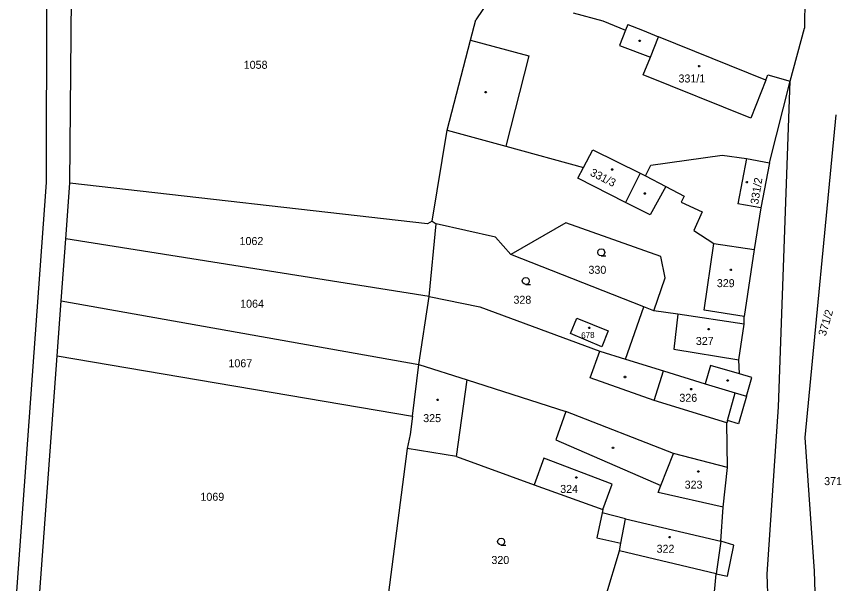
# Model space of a CAD drawing. Extents: x -812394 to -807601, y -1013097 to -1009266.
# Drawn here: x -811179.2 to -811005.4, y -1011411.9 to -1011291.2 of the extents above; entities that cross this region are included whole.
import ezdxf

# ---------------------------------------------------------------- set-up
doc = ezdxf.new("R2010")
doc.units = 0
for name, color, linetype in [('Default', 7, 'Continuous'), ('KN_HRANICE', 7, 'Continuous'), ('KN_KULTURY', 7, 'Continuous'), ('KN_PARCELY', 7, 'Continuous'), ('KN_SLUCKY', 7, 'Continuous')]:
    doc.layers.add(name, color=color, linetype=linetype)

# ---------------------------------------------------------------- blocks, each defined once
blk = doc.blocks.new('304')
at = {"layer": 'Default'}
blk.add_lwpolyline([(0, 0), (-0.38, 0.1), (-0.65, 0.37), (-0.75, 0.74), (-0.65, 1.11), (-0.38, 1.38), (-0.01, 1.48), (0.36, 1.38), (0.63, 1.11), (0.73, 0.73), (0.63, 0.35), (0.36, 0.08), (-0.02, -0.02), (0.98, -0.02)], dxfattribs=at)
blk = doc.blocks.new('NAHRADNI_SYMBOL')
at = {"layer": 'Default'}
blk.add_lwpolyline([(0.09, 0.15), (0.18, 0), (0.09, -0.15), (-0.09, -0.15), (-0.18, 0), (-0.09, 0.15), (0.09, 0.15)], dxfattribs=at)
blk = doc.blocks.new('402')
at = {"layer": 'Default'}
blk.add_lwpolyline([(0.09, 0.15), (0.18, 0), (0.09, -0.15), (-0.09, -0.15), (-0.18, 0), (-0.09, 0.15), (0.09, 0.15)], dxfattribs=at)

msp = doc.modelspace()

# ---------------------------------------------------------------- linework, layer by layer
at = {"layer": 'KN_HRANICE'}
for p, q in [((-811172.71, -1011212.32), (-811172.89, -1011326.55)), ((-811167.89, -1011326.74), (-811167.33, -1011261.3)), ((-811011.7, -1011272.27), (-811011.75, -1011293.77)), ((-811078.49, -1011287.34), (-811081.65, -1011291.97)), ((-811060.91, -1011290.53), (-811054.65, -1011292.2)), ((-811082.78, -1011296.33), (-811081.65, -1011291.97)), ((-811054.65, -1011292.2), (-811049.79, -1011294.2)), ((-811049.3, -1011292.98), (-811049.79, -1011294.2)), ((-811049.3, -1011292.98), (-811046.23, -1011294.21)), ((-811046.23, -1011294.21), (-811042.77, -1011295.58)), ((-811014.86, -1011305), (-811011.75, -1011293.77)), ((-811087.72, -1011315.45), (-811082.78, -1011296.33)), ((-811019.97, -1011304.8), (-811042.77, -1011295.58)), ((-811019.97, -1011304.8), (-811019.54, -1011303.71)), ((-811019.54, -1011303.71), (-811014.86, -1011305)), ((-811019.24, -1011322.42), (-811014.86, -1011305)), ((-811017.29, -1011374.24), (-811014.86, -1011305)), ((-811011.64, -1011380.82), (-811005.05, -1011312.16)), ((-811090.93, -1011334.76), (-811087.72, -1011315.45)), ((-811087.72, -1011315.45), (-811075.23, -1011318.84)), ((-811075.23, -1011318.84), (-811058.77, -1011323.4)), ((-811058.77, -1011323.4), (-811056.78, -1011319.65)), ((-811056.78, -1011319.65), (-811046.67, -1011324.57)), ((-811044.44, -1011322.9), (-811029.3, -1011320.76)), ((-811029.3, -1011320.76), (-811024.13, -1011321.49)), ((-811024.13, -1011321.49), (-811019.24, -1011322.42)), ((-811019.24, -1011322.42), (-811021.08, -1011331.96)), ((-811059.96, -1011325.63), (-811058.77, -1011323.4)), ((-811045.56, -1011325.16), (-811044.44, -1011322.9)), ((-811049.8, -1011330.85), (-811059.96, -1011325.63)), ((-811046.67, -1011324.57), (-811049.8, -1011330.85)), ((-811046.67, -1011324.57), (-811045.56, -1011325.16)), ((-811045.56, -1011325.16), (-811041.24, -1011327.41)), ((-811172.89, -1011326.55), (-811179.25, -1011413.51)), ((-811168.76, -1011338.54), (-811167.89, -1011326.74)), ((-811091.86, -1011335.35), (-811167.89, -1011326.74)), ((-811041.24, -1011327.41), (-811037.33, -1011329.45)), ((-811037.33, -1011329.45), (-811038.01, -1011330.76)), ((-811038.01, -1011330.76), (-811033.52, -1011332.81)), ((-811033.52, -1011332.81), (-811035.32, -1011336.75)), ((-811021.08, -1011331.96), (-811022.45, -1011340.81)), ((-811090.93, -1011334.76), (-811091.86, -1011335.35)), ((-811090.93, -1011334.76), (-811090.07, -1011335.38)), ((-811091.55, -1011350.81), (-811090.07, -1011335.38)), ((-811077.44, -1011338.22), (-811090.07, -1011335.38)), ((-811062.47, -1011335.13), (-811074.19, -1011341.86)), ((-811042.3, -1011342.3), (-811062.47, -1011335.13)), ((-811074.19, -1011341.86), (-811077.44, -1011338.22)), ((-811035.32, -1011336.75), (-811031.07, -1011339.53)), ((-811169.72, -1011351.73), (-811168.76, -1011338.54)), ((-811091.55, -1011350.81), (-811168.76, -1011338.54)), ((-811031.07, -1011339.53), (-811022.45, -1011340.81)), ((-811022.45, -1011340.81), (-811024.57, -1011355.07)), ((-811045.94, -1011352.98), (-811074.19, -1011341.86)), ((-811041.39, -1011346.87), (-811042.3, -1011342.3)), ((-811043.78, -1011353.83), (-811041.39, -1011346.87)), ((-811170.58, -1011363.44), (-811169.72, -1011351.73)), ((-811169.72, -1011351.73), (-811093.71, -1011365.29)), ((-811093.71, -1011365.29), (-811091.55, -1011350.81)), ((-811091.55, -1011350.81), (-811080.75, -1011353.03)), ((-811080.75, -1011353.03), (-811055.28, -1011362.43)), ((-811049.84, -1011364.11), (-811045.94, -1011352.98)), ((-811043.78, -1011353.83), (-811045.94, -1011352.98)), ((-811038.69, -1011354.58), (-811043.78, -1011353.83)), ((-811024.6, -1011356.66), (-811038.69, -1011354.58)), ((-811024.6, -1011356.66), (-811024.57, -1011355.07)), ((-811025.7, -1011364.28), (-811024.6, -1011356.66)), ((-811055.28, -1011362.43), (-811049.84, -1011364.11)), ((-811174.26, -1011413.61), (-811170.58, -1011363.44)), ((-811170.58, -1011363.44), (-811095.07, -1011376.26)), ((-811049.84, -1011364.11), (-811041.76, -1011366.61)), ((-811025.62, -1011367.27), (-811025.7, -1011364.28)), ((-811095.07, -1011376.26), (-811093.71, -1011365.29)), ((-811093.71, -1011365.29), (-811083.43, -1011368.52)), ((-811041.76, -1011366.61), (-811032.86, -1011369.35)), ((-811022.94, -1011368.05), (-811025.62, -1011367.27)), ((-811085.72, -1011384.86), (-811083.43, -1011368.52)), ((-811083.43, -1011368.52), (-811062.49, -1011375.27)), ((-811032.86, -1011369.35), (-811026.48, -1011371.32)), ((-811024.09, -1011372.01), (-811022.94, -1011368.05)), ((-811026.48, -1011371.32), (-811024.09, -1011372.01)), ((-811024.09, -1011372.01), (-811025.79, -1011377.87)), ((-811019.73, -1011409.84), (-811017.29, -1011374.24)), ((-811095.07, -1011376.26), (-811095.55, -1011380.13)), ((-811039.64, -1011384.22), (-811062.49, -1011375.27)), ((-811028.16, -1011377.17), (-811028.29, -1011377.65)), ((-811028.16, -1011387.19), (-811028.29, -1011377.65)), ((-811025.79, -1011377.87), (-811028.16, -1011377.17)), ((-811095.55, -1011380.13), (-811096.21, -1011383.14)), ((-811009.67, -1011409.19), (-811011.64, -1011380.82)), ((-811096.21, -1011383.14), (-811100.57, -1011416.83)), ((-811085.72, -1011384.86), (-811096.21, -1011383.14)), ((-811085.72, -1011384.86), (-811069.2, -1011390.82)), ((-811067.16, -1011385.18), (-811069.2, -1011390.82)), ((-811052.68, -1011390.73), (-811067.16, -1011385.18)), ((-811028.16, -1011387.19), (-811039.64, -1011384.22)), ((-811029.04, -1011395.62), (-811028.16, -1011387.19)), ((-811069.2, -1011390.82), (-811054.6, -1011396.09)), ((-811054.6, -1011396.09), (-811052.68, -1011390.73)), ((-811029.55, -1011402.86), (-811029.04, -1011395.62)), ((-811054.76, -1011396.82), (-811055.92, -1011402.11)), ((-811054.6, -1011396.09), (-811054.76, -1011396.82)), ((-811049.83, -1011398.08), (-811054.76, -1011396.82)), ((-811049.83, -1011398.08), (-811029.55, -1011402.86)), ((-811055.92, -1011402.11), (-811050.8, -1011403.23)), ((-811051.11, -1011404.88), (-811050.8, -1011403.23)), ((-811026.8, -1011403.71), (-811029.55, -1011402.86)), ((-811028.15, -1011410.25), (-811026.8, -1011403.71)), ((-811054.01, -1011414.53), (-811051.11, -1011404.88)), ((-811008.13, -1011453.24), (-811009.67, -1011409.19)), ((-811031.22, -1011416.63), (-811030.55, -1011409.8)), ((-811030.55, -1011409.8), (-811028.15, -1011410.25)), ((-811018.24, -1011451.73), (-811019.73, -1011409.84))]:
    msp.add_line(p, q, dxfattribs=at)
msp.add_lwpolyline([(-811060.13, -1011355.42), (-811053.47, -1011358.13), (-811054.85, -1011361.53), (-811061.47, -1011358.7)], close=True, dxfattribs=at)
at = {"layer": 'KN_SLUCKY'}
for p, q in [((-811049.79, -1011294.2), (-811051.11, -1011297.48)), ((-811082.78, -1011296.33), (-811070.38, -1011299.66)), ((-811044.53, -1011299.95), (-811042.77, -1011295.58)), ((-811051.11, -1011297.48), (-811044.53, -1011299.95)), ((-811070.38, -1011299.66), (-811075.23, -1011318.84)), ((-811046.04, -1011303.68), (-811044.53, -1011299.95)), ((-811023.18, -1011312.89), (-811046.04, -1011303.68)), ((-811019.97, -1011304.8), (-811023.18, -1011312.89)), ((-811024.13, -1011321.49), (-811025.93, -1011331.1)), ((-811041.24, -1011327.41), (-811044.55, -1011333.47)), ((-811044.55, -1011333.47), (-811049.8, -1011330.85)), ((-811021.08, -1011331.96), (-811025.93, -1011331.1)), ((-811033.08, -1011353.73), (-811031.07, -1011339.53)), ((-811024.57, -1011355.07), (-811033.08, -1011353.73)), ((-811038.69, -1011354.58), (-811039.52, -1011362.03)), ((-811057.29, -1011368.07), (-811055.28, -1011362.43)), ((-811039.52, -1011362.03), (-811025.7, -1011364.28)), ((-811031.74, -1011365.5), (-811032.86, -1011369.35)), ((-811025.62, -1011367.27), (-811031.74, -1011365.5)), ((-811043.7, -1011372.93), (-811041.76, -1011366.61)), ((-811043.7, -1011372.93), (-811057.29, -1011368.07)), ((-811028.16, -1011377.17), (-811026.48, -1011371.32)), ((-811028.29, -1011377.65), (-811043.7, -1011372.93)), ((-811062.49, -1011375.27), (-811064.61, -1011381.29)), ((-811064.61, -1011381.29), (-811042.3, -1011391.02)), ((-811042.3, -1011391.02), (-811039.64, -1011384.22)), ((-811042.87, -1011392.48), (-811042.3, -1011391.02)), ((-811029.04, -1011395.62), (-811042.87, -1011392.48)), ((-811050.8, -1011403.23), (-811049.83, -1011398.08)), ((-811029.55, -1011402.86), (-811030.55, -1011409.8)), ((-811030.55, -1011409.8), (-811051.11, -1011404.88))]:
    msp.add_line(p, q, dxfattribs=at)

# ---------------------------------------------------------------- block references
at = {"layer": 'KN_KULTURY'}
for name, p in [('402', (-811046.8, -1011296.48)), ('402', (-811034.17, -1011301.82)), ('402', (-811079.52, -1011307.36)), ('402', (-811052.65, -1011323.83)), ('402', (-811024.02, -1011326.52)), ('402', (-811045.71, -1011328.93)), ('304', (-811054.95, -1011342.16)), ('402', (-811027.42, -1011345.16)), ('304', (-811071, -1011348.25)), ('402', (-811057.53, -1011357.46)), ('402', (-811032.14, -1011357.74)), ('402', (-811049.94, -1011367.93)), ('402', (-811028.1, -1011368.67)), ('402', (-811035.86, -1011370.53)), ('NAHRADNI_SYMBOL', (-811089.75, -1011372.79)), ('402', (-811052.48, -1011383)), ('402', (-811034.33, -1011388.04)), ('402', (-811060.25, -1011389.29)), ('304', (-811076.24, -1011403.67)), ('402', (-811040.46, -1011401.99))]:
    msp.add_blockref(name, p, dxfattribs=at)

# ---------------------------------------------------------------- texts
at = {"layer": 'KN_PARCELY'}
for s, p in [('1058', (-811130.94, -1011302.4)), ('331/1', (-811038.56, -1011305.31)), ('1062', (-811131.83, -1011339.87)), ('330', (-811057.69, -1011345.98)), ('329', (-811030.41, -1011348.82)), ('1064', (-811131.7, -1011353.2)), ('328', (-811073.63, -1011352.35)), ('327', (-811034.87, -1011361.11)), ('1067', (-811134.19, -1011365.86)), ('326', (-811038.37, -1011373.2)), ('325', (-811092.8, -1011377.52)), ('323', (-811037.25, -1011391.66)), ('371/1', (-811007.6, -1011390.91)), ('324', (-811063.69, -1011392.57)), ('1069', (-811140.14, -1011394.24)), ('322', (-811043.21, -1011405.29)), ('320', (-811078.31, -1011407.68))]:
    msp.add_text(s, height=1.7, dxfattribs=at).set_placement(p)
for s, height, rotation, p in [('331/3', 1.7, 333.404, (-811057.49, -1011325.01)), ('331/2', 1.7, 80.73, (-811021.62, -1011331.31)), ('371/2', 1.7, 73.51, (-811007.28, -1011359.34)), ('678', 1.27, 2.636, (-811059.2, -1011359.73))]:
    msp.add_text(s, height=height, rotation=rotation, dxfattribs=at).set_placement(p)

doc.saveas('drawing.dxf')
